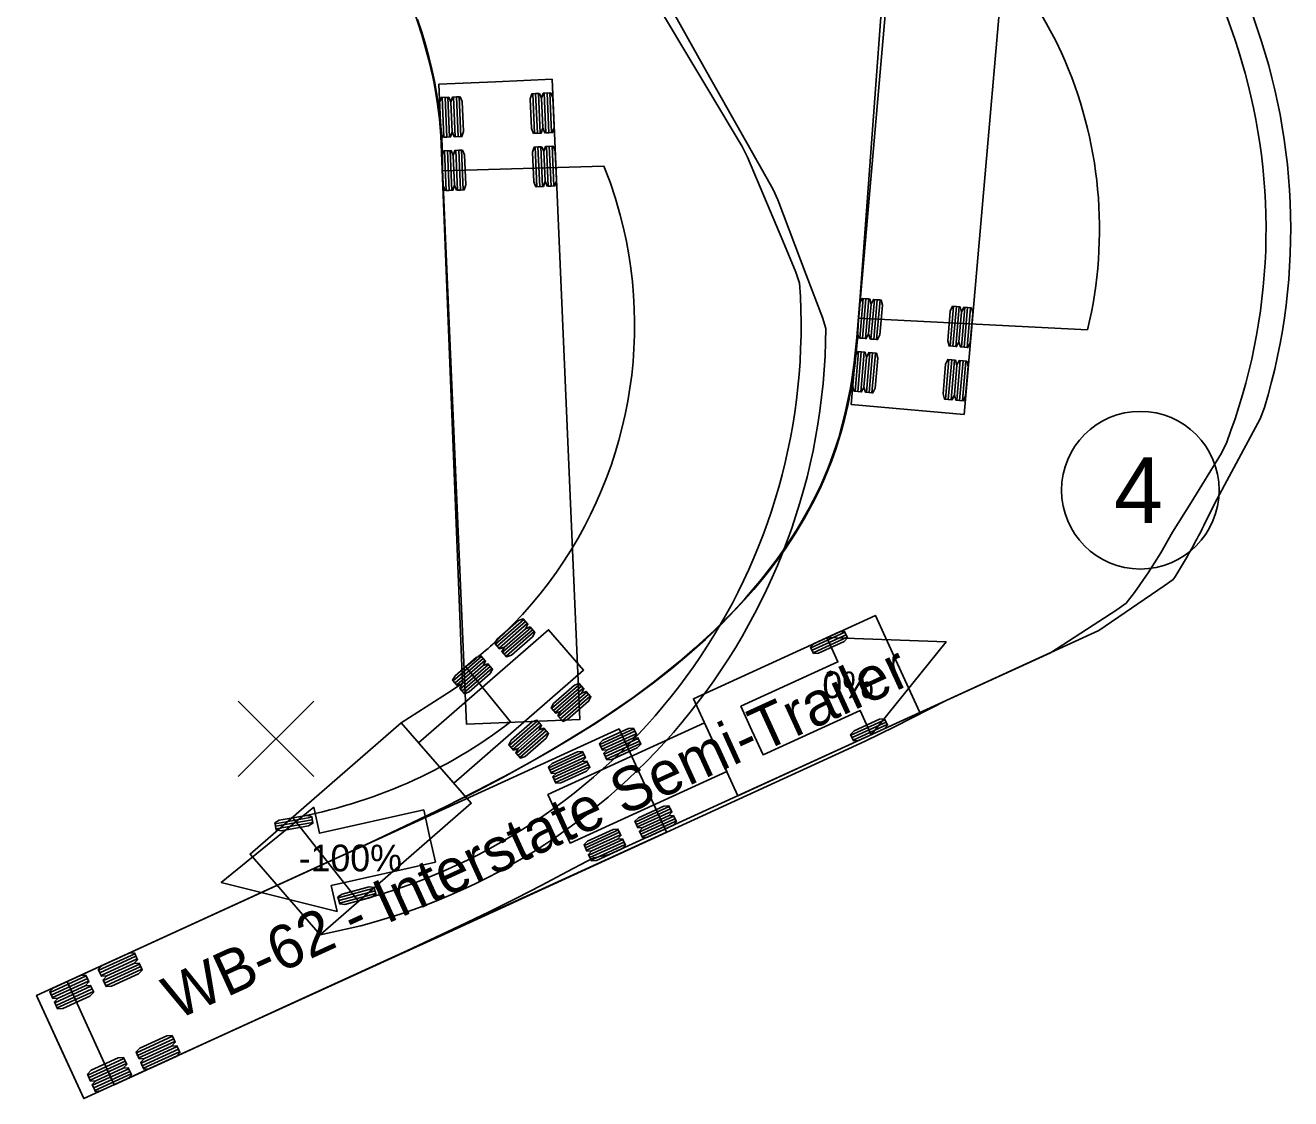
# Model space of a CAD drawing. Extents: x 1475900 to 1484331, y 375914 to 383395.
# Drawn here: x 1478591.7 to 1478686.5, y 379888.7 to 379969.1 of the extents above; entities that cross this region are included whole.
import ezdxf

# ---------------------------------------------------------------- set-up
doc = ezdxf.new("R2010")
doc.units = 0
doc.layers.add('PM_X_Misc', color=7, linetype='Continuous')
doc.layers.add('PM_X_Misc (Construction)', color=7, linetype='Continuous')

# ---------------------------------------------------------------- blocks, each defined once
blk = doc.blocks.new('ATRPTH_3')
at = {"layer": 'PM_X_Misc'}
for points in [[(375802.857, 96486.997), (375809.213, 96489.909), (375810.001, 96490.28), (375810.63, 96490.586), (375811.256, 96490.902), (375811.874, 96491.229), (375812.33, 96491.482), (375812.78, 96491.743), (375813.367, 96492.103), (375813.653, 96492.287), (375813.932, 96492.475), (375814.208, 96492.67), (375814.614, 96492.97), (375814.877, 96493.179), (375815.139, 96493.392), (375815.392, 96493.61), (375815.758, 96493.951), (375816.112, 96494.304), (375816.334, 96494.544), (375816.548, 96494.794), (375816.654, 96494.92), (375816.955, 96495.309), (375817.14, 96495.579), (375817.319, 96495.851), (375817.403, 96495.988), (375817.563, 96496.273), (375817.711, 96496.563), (375817.78, 96496.708), (375817.908, 96497.008), (375817.966, 96497.157), (375818.074, 96497.461), (375818.123, 96497.613), (375818.249, 96498.084), (375818.347, 96498.562), (375818.375, 96498.719), (375818.417, 96499.039), (375818.468, 96499.52), (375818.533, 96500.297), (375819.221, 96509.654)], [(375822.364, 96504.932), (375822.254, 96505.164), (375822.074, 96505.499), (375821.884, 96505.834), (375821.685, 96506.167), (375821.478, 96506.498), (375821.263, 96506.828), (375821.042, 96507.157), (375820.698, 96507.646), (375820.342, 96508.131), (375819.975, 96508.613), (375819.565, 96509.134), (375819.312, 96509.448), (375819.586, 96509.916), (375818.725, 96510.759), (375817.435, 96512.037), (375816.57, 96512.899), (375818.145, 96514.18), (375819.951, 96512.357), (375821.164, 96511.119), (375821.312, 96510.967), (375821.466, 96510.826)], [(375821.57, 96510.201), (375820.508, 96498.055), (375819.433, 96498.149), (375818.357, 96498.243), (375819.419, 96510.389), (375820.494, 96510.295), (375821.57, 96510.201), (375821.57, 96510.201)], [(375818.588, 96500.26), (375818.522, 96499.507), (375818.576, 96499.502), (375818.642, 96500.255), (375818.695, 96500.25), (375818.63, 96499.498), (375818.647, 96499.496), (375818.692, 96499.587), (375818.741, 96500.152), (375818.713, 96500.249), (375818.57, 96500.261), (375818.526, 96500.17), (375818.476, 96499.606), (375818.504, 96499.508), (375818.647, 96499.496)], [(375818.803, 96500.241), (375818.737, 96499.488), (375818.791, 96499.483), (375818.857, 96500.236), (375818.91, 96500.232), (375818.845, 96499.479), (375818.863, 96499.477), (375818.907, 96499.568), (375818.956, 96500.133), (375818.928, 96500.23), (375818.785, 96500.242), (375818.741, 96500.152), (375818.692, 96499.587), (375818.719, 96499.49), (375818.863, 96499.477)], [(375820.308, 96500.109), (375820.243, 96499.357), (375820.296, 96499.352), (375820.362, 96500.105), (375820.416, 96500.1), (375820.35, 96499.347), (375820.368, 96499.346), (375820.412, 96499.437), (375820.462, 96500.001), (375820.434, 96500.098), (375820.29, 96500.111), (375820.246, 96500.02), (375820.197, 96499.455), (375820.225, 96499.358), (375820.368, 96499.346)], [(375820.523, 96500.091), (375820.458, 96499.338), (375820.511, 96499.333), (375820.577, 96500.086), (375820.631, 96500.081), (375820.565, 96499.328), (375820.583, 96499.327), (375820.627, 96499.418), (375820.677, 96499.982), (375820.649, 96500.08), (375820.506, 96500.092), (375820.462, 96500.001), (375820.412, 96499.437), (375820.44, 96499.339), (375820.583, 96499.327)], [(375803.435, 96487.261), (375809.267, 96489.933), (375810.085, 96490.318), (375810.737, 96490.636), (375811.235, 96490.888), (375811.731, 96491.148), (375812.187, 96491.396), (375812.626, 96491.645), (375813.05, 96491.898), (375813.46, 96492.154), (375813.855, 96492.414), (375814.235, 96492.679), (375814.598, 96492.947), (375814.945, 96493.219), (375815.274, 96493.495), (375815.587, 96493.773), (375815.883, 96494.055), (375816.161, 96494.339), (375816.337, 96494.53), (375816.505, 96494.721), (375816.666, 96494.913), (375816.819, 96495.106), (375816.964, 96495.298), (375817.101, 96495.491), (375817.293, 96495.781), (375817.468, 96496.069), (375817.627, 96496.357), (375817.769, 96496.642), (375817.855, 96496.832), (375817.992, 96497.175), (375818.07, 96497.395), (375818.176, 96497.74), (375818.24, 96497.98), (375818.298, 96498.226), (375818.349, 96498.481), (375818.392, 96498.743), (375818.428, 96498.978), (375818.456, 96499.23), (375818.479, 96499.488), (375818.495, 96499.753), (375818.501, 96499.888), (375822.86, 96499.666)], [(375818.499, 96499.248), (375818.434, 96498.495), (375818.487, 96498.49), (375818.553, 96499.243), (375818.607, 96499.238), (375818.541, 96498.485), (375818.559, 96498.484), (375818.603, 96498.575), (375818.652, 96499.139), (375818.625, 96499.237), (375818.481, 96499.249), (375818.437, 96499.158), (375818.388, 96498.594), (375818.416, 96498.496), (375818.559, 96498.484)], [(375818.714, 96499.229), (375818.649, 96498.476), (375818.702, 96498.471), (375818.768, 96499.224), (375818.822, 96499.219), (375818.756, 96498.467), (375818.774, 96498.465), (375818.818, 96498.556), (375818.867, 96499.121), (375818.84, 96499.218), (375818.696, 96499.23), (375818.652, 96499.139), (375818.603, 96498.575), (375818.631, 96498.478), (375818.774, 96498.465)], [(375820.22, 96499.097), (375820.154, 96498.344), (375820.208, 96498.34), (375820.274, 96499.093), (375820.328, 96499.088), (375820.262, 96498.335), (375820.28, 96498.333), (375820.324, 96498.424), (375820.373, 96498.989), (375820.345, 96499.086), (375820.202, 96499.099), (375820.158, 96499.008), (375820.109, 96498.443), (375820.136, 96498.346), (375820.28, 96498.333)], [(375820.435, 96499.078), (375820.369, 96498.326), (375820.423, 96498.321), (375820.489, 96499.074), (375820.543, 96499.069), (375820.477, 96498.316), (375820.495, 96498.315), (375820.539, 96498.406), (375820.588, 96498.97), (375820.561, 96499.067), (375820.417, 96499.08), (375820.373, 96498.989), (375820.324, 96498.424), (375820.351, 96498.327), (375820.495, 96498.315)], [(375826.229, 96498.187), (375826.146, 96497.971), (375825.28, 96496.365), (375825.074, 96495.94)], [(375825.589, 96497.746), (375825.508, 96497.528), (375825.409, 96497.315), (375824.83, 96496.376), (375824.479, 96495.815), (375824.253, 96495.423), (375824.011, 96495.039), (375823.755, 96494.665), (375823.597, 96494.46), (375823.419, 96494.337), (375822.153, 96493.519), (375813.754, 96489.677), (375813.46, 96489.615), (375813.333, 96489.554), (375812.946, 96489.349), (375812.471, 96489.096), (375811.988, 96488.848), (375811.467, 96488.588), (375810.766, 96488.25), (375809.918, 96487.854), (375807.931, 96486.943), (375804.333, 96485.298), (375803.435, 96487.261)], [(375824.491, 96494.915), (375824.317, 96494.789), (375823.077, 96493.941), (375820.181, 96492.617), (375819.186, 96492.109), (375818.627, 96491.839), (375818.063, 96491.578), (375810.547, 96488.135), (375809.678, 96487.737), (375806.896, 96486.47), (375803.755, 96485.034), (375802.857, 96486.997)], [(375819.667, 96492.382), (375816.202, 96490.797), (375815.357, 96492.645), (375818.822, 96494.229), (375819.244, 96493.305), (375819.667, 96492.382), (375819.667, 96492.382)], [(375818.242, 96493.909), (375817.595, 96493.613), (375817.617, 96493.566), (375818.263, 96493.862), (375818.284, 96493.816), (375817.638, 96493.52), (375817.645, 96493.505), (375817.74, 96493.511), (375818.225, 96493.733), (375818.291, 96493.801), (375818.235, 96493.924), (375818.14, 96493.918), (375817.655, 96493.696), (375817.588, 96493.628), (375817.645, 96493.505)], [(375819.003, 96492.245), (375818.356, 96491.95), (375818.377, 96491.903), (375819.024, 96492.199), (375819.045, 96492.153), (375818.398, 96491.857), (375818.405, 96491.842), (375818.5, 96491.848), (375818.985, 96492.07), (375819.052, 96492.138), (375818.996, 96492.261), (375818.901, 96492.255), (375818.416, 96492.033), (375818.349, 96491.965), (375818.405, 96491.842)], [(375814.843, 96490.105), (375803.755, 96485.034), (375803.306, 96486.015), (375802.857, 96486.997), (375813.944, 96492.068), (375814.394, 96491.087), (375814.843, 96490.105), (375814.843, 96490.105)], [(375815.568, 96492.183), (375812.588, 96490.82), (375813.011, 96489.896), (375815.991, 96491.259), (375815.568, 96492.183)], [(375814.223, 96492.07), (375813.576, 96491.774), (375813.597, 96491.728), (375814.244, 96492.024), (375814.265, 96491.978), (375813.619, 96491.682), (375813.626, 96491.666), (375813.721, 96491.673), (375814.206, 96491.895), (375814.272, 96491.962), (375814.216, 96492.086), (375814.121, 96492.079), (375813.636, 96491.857), (375813.569, 96491.79), (375813.626, 96491.666)], [(375814.308, 96491.885), (375813.661, 96491.59), (375813.682, 96491.543), (375814.329, 96491.839), (375814.35, 96491.793), (375813.703, 96491.497), (375813.71, 96491.482), (375813.805, 96491.488), (375814.29, 96491.71), (375814.357, 96491.778), (375814.301, 96491.901), (375814.206, 96491.895), (375813.721, 96491.673), (375813.654, 96491.605), (375813.71, 96491.482)], [(375813.253, 96491.626), (375812.606, 96491.331), (375812.627, 96491.284), (375813.274, 96491.58), (375813.295, 96491.534), (375812.648, 96491.238), (375812.655, 96491.223), (375812.75, 96491.229), (375813.235, 96491.451), (375813.302, 96491.519), (375813.246, 96491.642), (375813.151, 96491.636), (375812.666, 96491.414), (375812.599, 96491.346), (375812.655, 96491.223)], [(375813.337, 96491.442), (375812.691, 96491.146), (375812.712, 96491.1), (375813.359, 96491.395), (375813.38, 96491.349), (375812.733, 96491.053), (375812.74, 96491.038), (375812.835, 96491.044), (375813.32, 96491.266), (375813.387, 96491.334), (375813.33, 96491.457), (375813.235, 96491.451), (375812.75, 96491.229), (375812.684, 96491.161), (375812.74, 96491.038)], [(375814.899, 96490.592), (375814.252, 96490.296), (375814.274, 96490.25), (375814.92, 96490.546), (375814.942, 96490.499), (375814.295, 96490.204), (375814.302, 96490.188), (375814.397, 96490.194), (375814.882, 96490.416), (375814.949, 96490.484), (375814.892, 96490.607), (375814.797, 96490.601), (375814.312, 96490.379), (375814.245, 96490.311), (375814.302, 96490.188)], [(375814.984, 96490.407), (375814.337, 96490.111), (375814.358, 96490.065), (375815.005, 96490.361), (375815.026, 96490.315), (375814.379, 96490.019), (375814.386, 96490.003), (375814.481, 96490.01), (375814.966, 96490.231), (375815.033, 96490.299), (375814.977, 96490.422), (375814.882, 96490.416), (375814.397, 96490.194), (375814.33, 96490.127), (375814.386, 96490.003)], [(375813.929, 96490.148), (375813.282, 96489.852), (375813.303, 96489.806), (375813.95, 96490.102), (375813.971, 96490.056), (375813.325, 96489.76), (375813.332, 96489.744), (375813.427, 96489.751), (375813.912, 96489.973), (375813.978, 96490.04), (375813.922, 96490.163), (375813.827, 96490.157), (375813.342, 96489.935), (375813.275, 96489.868), (375813.332, 96489.744)], [(375814.014, 96489.963), (375813.367, 96489.667), (375813.388, 96489.621), (375814.035, 96489.917), (375814.056, 96489.871), (375813.409, 96489.575), (375813.416, 96489.56), (375813.511, 96489.566), (375813.996, 96489.788), (375814.063, 96489.856), (375814.007, 96489.979), (375813.912, 96489.973), (375813.427, 96489.751), (375813.36, 96489.683), (375813.416, 96489.56)], [(375804.725, 96487.792), (375804.038, 96487.477), (375804.06, 96487.428), (375804.747, 96487.743), (375804.77, 96487.694), (375804.083, 96487.379), (375804.09, 96487.363), (375804.191, 96487.37), (375804.706, 96487.605), (375804.777, 96487.677), (375804.717, 96487.808), (375804.616, 96487.802), (375804.101, 96487.566), (375804.03, 96487.494), (375804.09, 96487.363)], [(375803.801, 96487.369), (375803.114, 96487.055), (375803.136, 96487.006), (375803.823, 96487.32), (375803.846, 96487.271), (375803.159, 96486.957), (375803.166, 96486.94), (375803.267, 96486.947), (375803.782, 96487.183), (375803.853, 96487.255), (375803.793, 96487.386), (375803.693, 96487.379), (375803.177, 96487.143), (375803.106, 96487.071), (375803.166, 96486.94)], [(375804.815, 96487.595), (375804.127, 96487.281), (375804.15, 96487.232), (375804.837, 96487.546), (375804.86, 96487.497), (375804.172, 96487.183), (375804.18, 96487.167), (375804.281, 96487.173), (375804.796, 96487.409), (375804.867, 96487.481), (375804.807, 96487.612), (375804.706, 96487.605), (375804.191, 96487.37), (375804.12, 96487.298), (375804.18, 96487.167)], [(375803.891, 96487.173), (375803.204, 96486.859), (375803.226, 96486.809), (375803.913, 96487.124), (375803.936, 96487.075), (375803.248, 96486.76), (375803.256, 96486.744), (375803.357, 96486.751), (375803.872, 96486.986), (375803.943, 96487.058), (375803.883, 96487.189), (375803.782, 96487.183), (375803.267, 96486.947), (375803.196, 96486.875), (375803.256, 96486.744)], [(375805.443, 96486.221), (375804.756, 96485.907), (375804.779, 96485.858), (375805.466, 96486.172), (375805.488, 96486.123), (375804.801, 96485.809), (375804.809, 96485.792), (375804.909, 96485.799), (375805.425, 96486.035), (375805.496, 96486.107), (375805.436, 96486.237), (375805.335, 96486.231), (375804.82, 96485.995), (375804.749, 96485.923), (375804.809, 96485.792)], [(375805.533, 96486.025), (375804.846, 96485.71), (375804.868, 96485.661), (375805.556, 96485.976), (375805.578, 96485.927), (375804.891, 96485.612), (375804.898, 96485.596), (375804.999, 96485.603), (375805.515, 96485.838), (375805.585, 96485.91), (375805.526, 96486.041), (375805.425, 96486.035), (375804.909, 96485.799), (375804.838, 96485.727), (375804.898, 96485.596)], [(375804.519, 96485.799), (375803.832, 96485.484), (375803.855, 96485.435), (375804.542, 96485.749), (375804.564, 96485.7), (375803.877, 96485.386), (375803.885, 96485.37), (375803.985, 96485.376), (375804.501, 96485.612), (375804.572, 96485.684), (375804.512, 96485.815), (375804.411, 96485.808), (375803.896, 96485.573), (375803.825, 96485.501), (375803.885, 96485.37)], [(375804.609, 96485.602), (375803.922, 96485.288), (375803.944, 96485.239), (375804.632, 96485.553), (375804.654, 96485.504), (375803.967, 96485.19), (375803.974, 96485.173), (375804.075, 96485.18), (375804.591, 96485.416), (375804.662, 96485.488), (375804.602, 96485.619), (375804.501, 96485.612), (375803.985, 96485.376), (375803.915, 96485.304), (375803.974, 96485.173)]]:
    blk.add_lwpolyline(points, dxfattribs=at)
for centre, radius, start, end in [((375814.928, 96501.575), 11.798, 343.3131, 58.9651), ((375814.928, 96501.575), 11.328, 340.2453, 54.7511), ((375814.928, 96501.575), 8.159, 346.4692, 24.2952), ((375814.544, 96501.26), 11.798, 327.4669, 333.1981)]:
    blk.add_arc(centre, radius, start, end, dxfattribs=at)
at = {"layer": 'PM_X_Misc (Construction)'}
blk.add_lwpolyline([(375816.472, 96492.038), (375816.261, 96492.5), (375818.109, 96493.345), (375817.898, 96493.807), (375820.168, 96493.728), (375818.743, 96491.959), (375818.532, 96492.421), (375816.684, 96491.576), (375816.472, 96492.038)], dxfattribs=at)
blk.add_circle((375823.864, 96496.612), 1.5, dxfattribs=at)
at = {"layer": 'PM_X_Misc'}
blk.add_text('WB-62 - Interstate Semi-Trailer', height=0.83333, rotation=24.5802, dxfattribs=at).set_placement((375805.517, 96486.522))
at = {"layer": 'PM_X_Misc (Construction)'}
for s, height, p in [('4', 1.25, (375823.364, 96495.987)), ('0%', 0.508, (375817.812, 96492.654))]:
    blk.add_text(s, height=height, dxfattribs=at).set_placement(p)
blk = doc.blocks.new('ATRPTH_6')
at = {"layer": 'PM_X_Misc'}
for p, q in [((375811.764, 96493.893), (375812.102, 96494.247)), ((375811.877, 96492.202), (375811.021, 96493.254)), ((375808.979, 96488.799), (375807.736, 96490.378))]:
    blk.add_line(p, q, dxfattribs=at)
for points in [[(375808.254, 96488.154), (375806.92, 96489.687), (375809.795, 96492.188), (375810.745, 96492.792), (375810.962, 96492.942), (375810.551, 96503.356), (375810.522, 96503.68), (375810.481, 96504.001), (375810.427, 96504.321), (375810.395, 96504.48), (375810.32, 96504.797), (375810.187, 96505.276), (375810.033, 96505.747)], [(375791.236, 96529.164), (375810.344, 96511.018), (375810.63, 96510.733), (375810.912, 96510.439), (375811.301, 96510.028), (375811.412, 96509.918), (375814.021, 96507.435), (375814.871, 96505.891), (375815.61, 96504.565), (375816.454, 96503.073), (375816.876, 96502.333), (375816.965, 96502.136), (375817.506, 96500.707), (375817.816, 96499.901), (375817.877, 96499.69)], [(375813.964, 96501.847), (375813.874, 96502.161), (375813.771, 96502.471), (375813.655, 96502.777), (375810.582, 96502.688), (375810.584, 96502.991), (375810.572, 96503.302), (375810.546, 96503.622), (375810.505, 96503.949), (375810.469, 96504.172), (375810.427, 96504.398), (375810.377, 96504.626), (375810.321, 96504.857), (375810.258, 96505.092), (375810.187, 96505.328), (375810.109, 96505.567)], [(375791.696, 96528.727), (375803.472, 96517.539), (375804.191, 96516.841), (375804.916, 96516.123), (375805.582, 96515.454), (375809.308, 96511.915), (375809.621, 96511.628), (375810.02, 96511.242), (375810.265, 96511.007), (375813.286, 96508.135), (375813.529, 96507.742), (375814.425, 96506.261), (375815.634, 96504.243), (375816.286, 96503.149), (375816.385, 96502.95), (375817.057, 96501.355), (375817.305, 96500.763), (375817.376, 96500.55), (375817.394, 96500.299)], [(375811.04, 96492.157), (375810.511, 96504.337), (375811.589, 96504.384), (375812.668, 96504.431), (375813.197, 96492.25), (375812.118, 96492.204), (375811.04, 96492.157), (375811.04, 96492.157)], [(375810.717, 96503.332), (375810.684, 96504.087), (375810.63, 96504.085), (375810.663, 96503.33), (375810.609, 96503.328), (375810.576, 96504.083), (375810.558, 96504.082), (375810.526, 96503.986), (375810.551, 96503.42), (375810.591, 96503.327), (375810.735, 96503.333), (375810.766, 96503.429), (375810.742, 96503.995), (375810.702, 96504.088), (375810.558, 96504.082)], [(375810.932, 96503.342), (375810.899, 96504.097), (375810.846, 96504.094), (375810.878, 96503.339), (375810.824, 96503.337), (375810.792, 96504.092), (375810.774, 96504.091), (375810.742, 96503.995), (375810.766, 96503.429), (375810.806, 96503.336), (375810.95, 96503.342), (375810.982, 96503.438), (375810.957, 96504.005), (375810.917, 96504.097), (375810.774, 96504.091)], [(375812.442, 96503.407), (375812.409, 96504.162), (375812.355, 96504.16), (375812.388, 96503.405), (375812.334, 96503.403), (375812.301, 96504.157), (375812.284, 96504.157), (375812.252, 96504.061), (375812.276, 96503.495), (375812.316, 96503.402), (375812.46, 96503.408), (375812.492, 96503.504), (375812.467, 96504.07), (375812.427, 96504.163), (375812.284, 96504.157)], [(375812.658, 96503.417), (375812.625, 96504.172), (375812.571, 96504.169), (375812.604, 96503.414), (375812.55, 96503.412), (375812.517, 96504.167), (375812.499, 96504.166), (375812.467, 96504.07), (375812.492, 96503.504), (375812.532, 96503.411), (375812.676, 96503.417), (375812.708, 96503.513), (375812.683, 96504.079), (375812.643, 96504.172), (375812.499, 96504.166)], [(375810.761, 96502.317), (375810.728, 96503.072), (375810.674, 96503.07), (375810.707, 96502.315), (375810.653, 96502.313), (375810.62, 96503.067), (375810.602, 96503.067), (375810.57, 96502.971), (375810.595, 96502.405), (375810.635, 96502.312), (375810.779, 96502.318), (375810.81, 96502.414), (375810.786, 96502.98), (375810.746, 96503.073), (375810.602, 96503.067)], [(375810.976, 96502.327), (375810.944, 96503.082), (375810.89, 96503.079), (375810.922, 96502.324), (375810.868, 96502.322), (375810.836, 96503.077), (375810.818, 96503.076), (375810.786, 96502.98), (375810.81, 96502.414), (375810.85, 96502.321), (375810.994, 96502.327), (375811.026, 96502.423), (375811.002, 96502.99), (375810.962, 96503.082), (375810.818, 96503.076)], [(375812.486, 96502.392), (375812.453, 96503.147), (375812.399, 96503.145), (375812.432, 96502.39), (375812.378, 96502.387), (375812.346, 96503.142), (375812.328, 96503.142), (375812.296, 96503.046), (375812.32, 96502.479), (375812.36, 96502.387), (375812.504, 96502.393), (375812.536, 96502.489), (375812.511, 96503.055), (375812.471, 96503.148), (375812.328, 96503.142)], [(375812.702, 96502.402), (375812.669, 96503.156), (375812.615, 96503.154), (375812.648, 96502.399), (375812.594, 96502.397), (375812.561, 96503.152), (375812.543, 96503.151), (375812.511, 96503.055), (375812.536, 96502.489), (375812.576, 96502.396), (375812.72, 96502.402), (375812.752, 96502.498), (375812.727, 96503.064), (375812.687, 96503.157), (375812.543, 96503.151)], [(375811.658, 96493.606), (375812.195, 96494.073), (375812.161, 96494.111), (375811.625, 96493.645), (375811.591, 96493.683), (375812.128, 96494.15), (375812.117, 96494.162), (375812.028, 96494.13), (375811.625, 96493.78), (375811.58, 96493.696), (375811.669, 96493.593), (375811.759, 96493.626), (375812.161, 96493.976), (375812.206, 96494.06), (375812.117, 96494.162)], [(375810.795, 96491.038), (375813.267, 96493.188), (375812.601, 96493.955), (375810.128, 96491.804), (375810.795, 96491.038)], [(375811.791, 96493.453), (375812.328, 96493.92), (375812.295, 96493.958), (375811.758, 96493.491), (375811.725, 96493.53), (375812.261, 96493.996), (375812.25, 96494.009), (375812.161, 96493.976), (375811.759, 96493.626), (375811.714, 96493.542), (375811.803, 96493.44), (375811.892, 96493.473), (375812.294, 96493.823), (375812.339, 96493.907), (375812.25, 96494.009)], [(375810.853, 96492.906), (375811.39, 96493.373), (375811.356, 96493.411), (375810.82, 96492.944), (375810.787, 96492.983), (375811.323, 96493.449), (375811.312, 96493.462), (375811.223, 96493.429), (375810.82, 96493.079), (375810.775, 96492.996), (375810.864, 96492.893), (375810.954, 96492.926), (375811.356, 96493.276), (375811.401, 96493.36), (375811.312, 96493.462)], [(375810.987, 96492.753), (375811.523, 96493.219), (375811.49, 96493.258), (375810.953, 96492.791), (375810.92, 96492.829), (375811.457, 96493.296), (375811.445, 96493.309), (375811.356, 96493.276), (375810.954, 96492.926), (375810.909, 96492.842), (375810.998, 96492.74), (375811.087, 96492.773), (375811.489, 96493.123), (375811.534, 96493.207), (375811.445, 96493.309)], [(375812.725, 96492.38), (375813.262, 96492.846), (375813.228, 96492.885), (375812.692, 96492.418), (375812.658, 96492.456), (375813.195, 96492.923), (375813.184, 96492.936), (375813.094, 96492.903), (375812.692, 96492.553), (375812.647, 96492.469), (375812.736, 96492.367), (375812.825, 96492.4), (375813.228, 96492.75), (375813.273, 96492.834), (375813.184, 96492.936)], [(375812.858, 96492.226), (375813.395, 96492.693), (375813.362, 96492.731), (375812.825, 96492.265), (375812.792, 96492.303), (375813.328, 96492.77), (375813.317, 96492.782), (375813.228, 96492.75), (375812.825, 96492.4), (375812.78, 96492.316), (375812.869, 96492.213), (375812.959, 96492.246), (375813.361, 96492.596), (375813.406, 96492.68), (375813.317, 96492.782)], [(375811.92, 96491.68), (375812.457, 96492.146), (375812.423, 96492.185), (375811.887, 96491.718), (375811.853, 96491.756), (375812.39, 96492.223), (375812.379, 96492.236), (375812.29, 96492.203), (375811.887, 96491.853), (375811.842, 96491.769), (375811.931, 96491.667), (375812.02, 96491.7), (375812.423, 96492.05), (375812.468, 96492.133), (375812.379, 96492.236)], [(375806.92, 96489.687), (375809.795, 96492.188), (375811.128, 96490.654), (375808.254, 96488.154), (375807.587, 96488.921), (375806.92, 96489.687), (375806.92, 96489.687)], [(375812.053, 96491.526), (375812.59, 96491.993), (375812.557, 96492.031), (375812.02, 96491.565), (375811.987, 96491.603), (375812.523, 96492.07), (375812.512, 96492.082), (375812.423, 96492.05), (375812.02, 96491.7), (375811.976, 96491.616), (375812.064, 96491.513), (375812.154, 96491.546), (375812.556, 96491.896), (375812.601, 96491.98), (375812.512, 96492.082)], [(375807.412, 96490.166), (375808.112, 96490.289), (375808.104, 96490.339), (375807.403, 96490.216), (375807.394, 96490.266), (375808.095, 96490.389), (375808.092, 96490.406), (375807.998, 96490.424), (375807.473, 96490.331), (375807.391, 96490.282), (375807.415, 96490.149), (375807.508, 96490.131), (375808.034, 96490.224), (375808.115, 96490.273), (375808.092, 96490.406)], [(375808.623, 96488.757), (375809.31, 96488.939), (375809.297, 96488.989), (375808.61, 96488.807), (375808.597, 96488.856), (375809.284, 96489.038), (375809.28, 96489.054), (375809.185, 96489.064), (375808.67, 96488.927), (375808.592, 96488.872), (375808.627, 96488.741), (375808.722, 96488.731), (375809.237, 96488.868), (375809.315, 96488.923), (375809.28, 96489.054)]]:
    blk.add_lwpolyline(points, dxfattribs=at)
for centre, radius, start, end in [((375806.078, 96499.75), 8.16, 317.5861, 14.8908), ((375806.079, 96499.75), 11.328, 284.8339, 2.7784), ((375806.079, 96499.75), 11.798, 280.6199, 359.7107), ((375806.079, 96499.75), 8.162, 307.2665, 314.144), ((375806.079, 96499.75), 9.518, 280.0223, 307.5321)]:
    blk.add_arc(centre, radius, start, end, dxfattribs=at)
at = {"layer": 'PM_X_Misc (Construction)'}
for p, q in [((375806.693, 96491.161), (375808.133, 96492.6)), ((375808.133, 96491.161), (375806.693, 96492.6))]:
    blk.add_line(p, q, dxfattribs=at)
blk.add_lwpolyline([(375810.336, 96490.031), (375810.447, 96489.536), (375808.464, 96489.092), (375808.575, 96488.596), (375806.37, 96489.144), (375808.132, 96490.579), (375808.242, 96490.083), (375810.225, 96490.527), (375810.336, 96490.031)], dxfattribs=at)
blk.add_text('-100%', height=0.508, dxfattribs=at).set_placement((375807.845, 96489.359))

msp = doc.modelspace()

# ---------------------------------------------------------------- block references
at = {"layer": 'PM_X_Misc', "xscale": 3.937007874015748, "yscale": 3.937007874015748}
for name in ['ATRPTH_6', 'ATRPTH_3']:
    msp.add_blockref(name, (-946.236, 26.336), dxfattribs=at)

doc.saveas('drawing.dxf')
